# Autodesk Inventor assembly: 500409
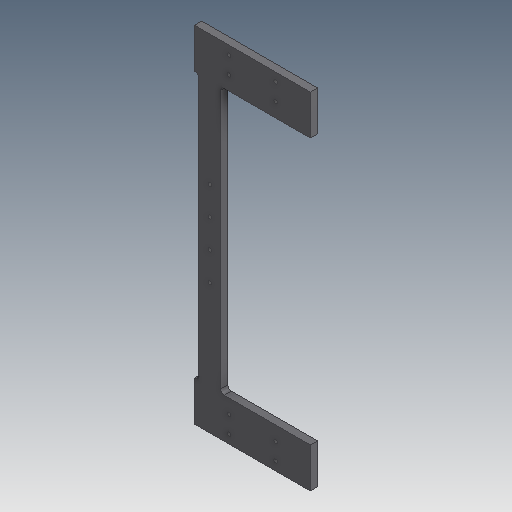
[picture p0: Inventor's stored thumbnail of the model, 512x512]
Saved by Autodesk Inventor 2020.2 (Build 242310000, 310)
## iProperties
Created: 2000-01
Part Number: 500409
Document SubType Name: Assembly
Designer: glanglot
Mass: 573.757 g
Surface Area: 299.43 cm^2
Volume: 72.997 cm^3
Density: 7.86 g/cm^3
Control State: 0
Checked Out: False
Master: False
Shininess: 0.0
Length Units: 11269
Angle Units: 11279
Time Units: 11290
Mass Units: 11283
Length Display Precision: 3
Angle Display Precision: 2
Compacted: True
Dimensions: 304x6,4x102 mm
Mass: 0,574 kg
Density: 0.0
Volumn: 0.0
Area: 0.0
PropertySet Name: Model Information
Author: glanglot
Revision Number: -
Title: 500409
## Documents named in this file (2)
- D:\07 - DEMODATEN\OTX 2019 - Dataset - UPDATE - Dez2019\Designs\07-Packing machine\500409.iam
- D:\07 - DEMODATEN\OTX 2019 - Dataset - UPDATE - Dez2019\Designs\07-Packing machine\Parts\ADSK-011386.ipt
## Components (1 placed, 1 different names)
1. ADSK-011386:1
